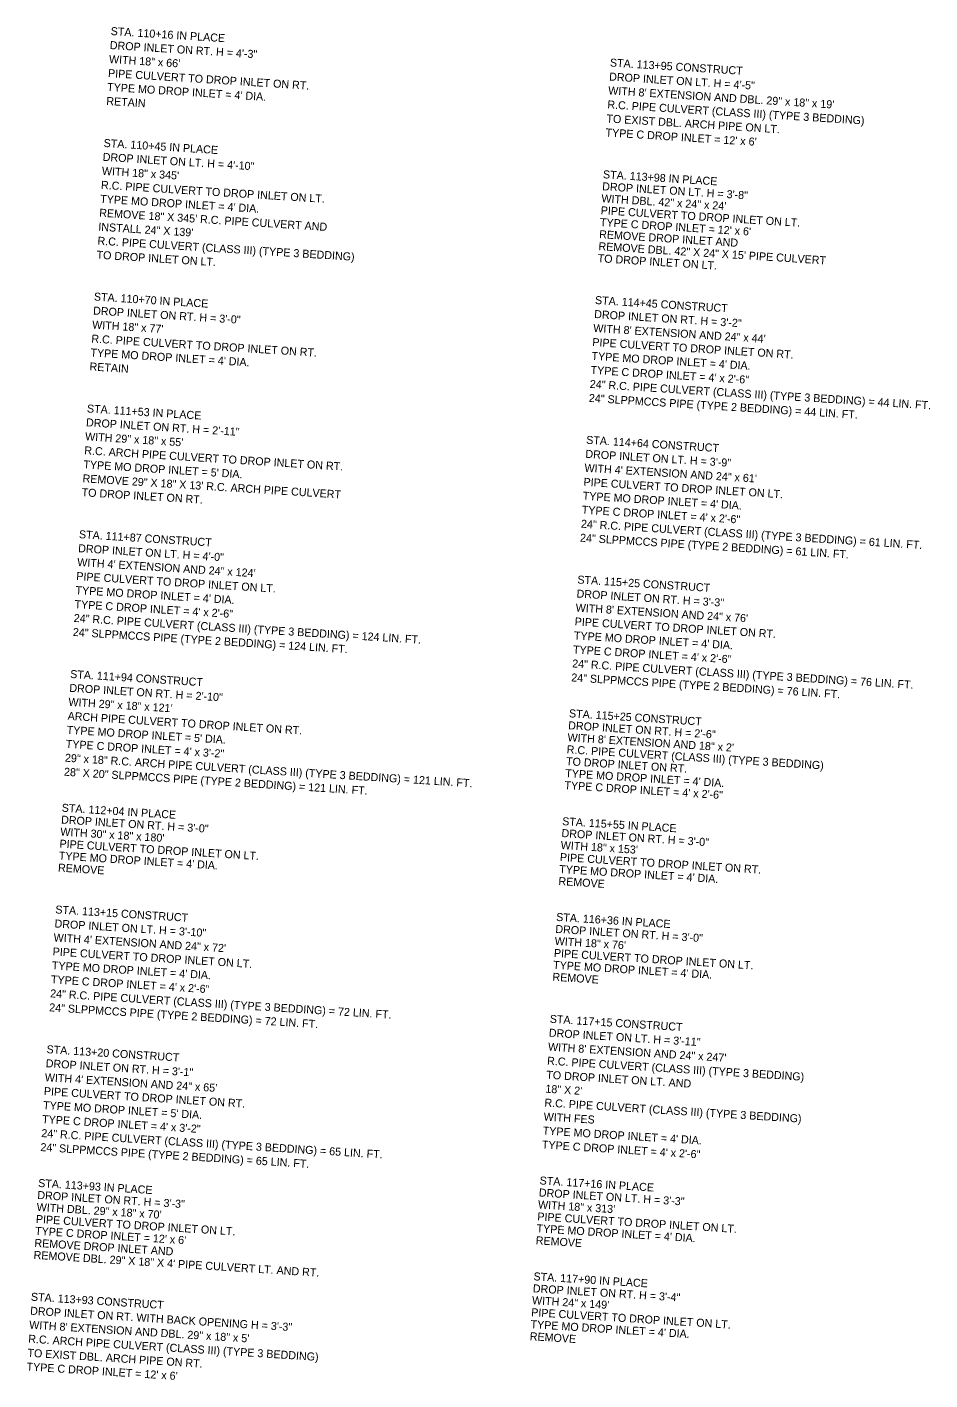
# Model space of a CAD drawing. Extents: x 660729 to 669183, y 641696 to 736523.
# Drawn here: x 660729 to 661406, y 641803 to 642818 of the extents above; entities that cross this region are included whole.
import ezdxf

# ---------------------------------------------------------------- set-up
doc = ezdxf.new("R2010")
doc.units = 0
doc.layers.add('T_Indications', color=7, linetype='Continuous')

msp = doc.modelspace()

# ---------------------------------------------------------------- texts
at = {"layer": 'T_Indications'}
for s, p in [('STA. 110+16 IN PLACE', (660791.3, 642812)), ('DROP INLET ON RT. H = 4\'-3"', (660790.6, 642801.5)), ('WITH 18" x 66\'', (660790, 642791)), ('STA. 113+95 CONSTRUCT', (661165.5, 642788.4)), ('PIPE CULVERT TO DROP INLET ON RT.', (660789.3, 642780.5)), ('DROP INLET ON LT. H = 4\'-5"', (661164.9, 642777.9)), ("TYPE MO DROP INLET = 4' DIA.", (660788.6, 642770.1)), ('WITH 8\' EXTENSION AND DBL. 29" x 18" x 19\'', (661164.2, 642767.5)), ('RETAIN', (660788, 642759.6)), ('R.C. PIPE CULVERT (CLASS III) (TYPE 3 BEDDING)', (661163.6, 642757)), ('TO EXIST DBL. ARCH PIPE ON LT.', (661162.9, 642746.5)), ("TYPE C DROP INLET = 12' x 6'", (661162.2, 642736)), ('STA. 110+45 IN PLACE', (660786, 642728.1)), ('DROP INLET ON LT. H = 4\'-10"', (660785.3, 642717.7)), ('WITH 18" x 345\'', (660784.7, 642707.2)), ('STA. 113+98 IN PLACE', (661160.3, 642704.6)), ('R.C. PIPE CULVERT TO DROP INLET ON LT.', (660784, 642696.7)), ('DROP INLET ON LT. H = 3\'-8"', (661159.7, 642695.6)), ("TYPE MO DROP INLET = 4' DIA.", (660783.4, 642686.2)), ('WITH DBL. 42" x 24" x 24\'', (661159.1, 642686.6)), ('REMOVE 18" X 345\' R.C. PIPE CULVERT AND', (660782.7, 642675.8)), ('PIPE CULVERT TO DROP INLET ON LT.', (661158.6, 642677.6)), ('INSTALL 24" X 139\'', (660782, 642665.3)), ("TYPE C DROP INLET = 12' x 6'", (661158, 642668.7)), ('R.C. PIPE CULVERT (CLASS III) (TYPE 3 BEDDING)', (660781.4, 642654.8)), ('REMOVE DROP INLET AND', (661157.4, 642659.7)), ('TO DROP INLET ON LT.', (660780.7, 642644.3)), ('REMOVE DBL. 42" X 24" X 15\' PIPE CULVERT', (661156.9, 642650.7)), ('TO DROP INLET ON LT.', (661156.3, 642641.7)), ('STA. 110+70 IN PLACE', (660778.7, 642612.9)), ('DROP INLET ON RT. H = 3\'-0"', (660778.1, 642602.4)), ('STA. 114+45 CONSTRUCT', (661154.3, 642610.3)), ('WITH 18" x 77\'', (660777.4, 642591.9)), ('DROP INLET ON RT. H = 3\'-2"', (661153.7, 642599.8)), ('R.C. PIPE CULVERT TO DROP INLET ON RT.', (660776.8, 642581.4)), ('WITH 8\' EXTENSION AND 24" x 44\'', (661153, 642589.3)), ('PIPE CULVERT TO DROP INLET ON RT.', (661152.3, 642578.8)), ("TYPE MO DROP INLET = 4' DIA.", (660776.1, 642571)), ("TYPE MO DROP INLET = 4' DIA.", (661151.7, 642568.4)), ('RETAIN', (660775.4, 642560.5)), ('TYPE C DROP INLET = 4\' x 2\'-6"', (661151, 642557.9)), ('24" R.C. PIPE CULVERT (CLASS III) (TYPE 3 BEDDING) = 44 LIN. FT.', (661150.4, 642547.4)), ('24" SLPPMCCS PIPE (TYPE 2 BEDDING) = 44 LIN. FT.', (661149.7, 642536.9)), ('STA. 111+53 IN PLACE', (660773.5, 642529)), ('DROP INLET ON RT. H = 2\'-11"', (660772.8, 642518.6)), ('WITH 29" x 18" x 55\'', (660772.1, 642508.1)), ('STA. 114+64 CONSTRUCT', (661147.7, 642505.5)), ('R.C. ARCH PIPE CULVERT TO DROP INLET ON RT.', (660771.5, 642497.6)), ('DROP INLET ON LT. H = 3\'-9"', (661147.1, 642495)), ("TYPE MO DROP INLET = 5' DIA.", (660770.8, 642487.1)), ('WITH 4\' EXTENSION AND 24" x 61\'', (661146.4, 642484.5)), ('REMOVE 29" X 18" X 13\' R.C. ARCH PIPE CULVERT', (660770.2, 642476.6)), ('PIPE CULVERT TO DROP INLET ON LT.', (661145.7, 642474)), ('TO DROP INLET ON RT.', (660769.5, 642466.2)), ("TYPE MO DROP INLET = 4' DIA.", (661145.1, 642463.6)), ('TYPE C DROP INLET = 4\' x 2\'-6"', (661144.4, 642453.1)), ('24" R.C. PIPE CULVERT (CLASS III) (TYPE 3 BEDDING) = 61 LIN. FT.', (661143.8, 642442.6)), ('STA. 111+87 CONSTRUCT', (660767.5, 642434.7)), ('24" SLPPMCCS PIPE (TYPE 2 BEDDING) = 61 LIN. FT.', (661143.1, 642432.1)), ('DROP INLET ON LT. H = 4\'-0"', (660766.9, 642424.2)), ('WITH 4\' EXTENSION AND 24" x 124\'', (660766.2, 642413.8)), ('PIPE CULVERT TO DROP INLET ON LT.', (660765.5, 642403.3)), ('STA. 115+25 CONSTRUCT', (661141.1, 642400.7)), ("TYPE MO DROP INLET = 4' DIA.", (660764.9, 642392.8)), ('DROP INLET ON RT. H = 3\'-3"', (661140.5, 642390.2)), ('TYPE C DROP INLET = 4\' x 2\'-6"', (660764.2, 642382.3)), ('WITH 8\' EXTENSION AND 24" x 76\'', (661139.8, 642379.7)), ('24" R.C. PIPE CULVERT (CLASS III) (TYPE 3 BEDDING) = 124 LIN. FT.', (660763.6, 642371.9)), ('PIPE CULVERT TO DROP INLET ON RT.', (661139.1, 642369.3)), ('24" SLPPMCCS PIPE (TYPE 2 BEDDING) = 124 LIN. FT.', (660762.9, 642361.4)), ("TYPE MO DROP INLET = 4' DIA.", (661138.5, 642358.8)), ('TYPE C DROP INLET = 4\' x 2\'-6"', (661137.8, 642348.3)), ('24" R.C. PIPE CULVERT (CLASS III) (TYPE 3 BEDDING) = 76 LIN. FT.', (661137.2, 642337.8)), ('STA. 111+94 CONSTRUCT', (660760.9, 642329.9)), ('DROP INLET ON RT. H = 2\'-10"', (660760.3, 642319.5)), ('24" SLPPMCCS PIPE (TYPE 2 BEDDING) = 76 LIN. FT.', (661136.5, 642327.3)), ('WITH 29" x 18" x 121\'', (660759.6, 642309)), ('ARCH PIPE CULVERT TO DROP INLET ON RT.', (660759, 642298.5)), ('STA. 115+25 CONSTRUCT', (661134.8, 642300.4)), ("TYPE MO DROP INLET = 5' DIA.", (660758.3, 642288)), ('DROP INLET ON RT. H = 2\'-6"', (661134.2, 642291.4)), ('TYPE C DROP INLET = 4\' x 3\'-2"', (660757.6, 642277.5)), ('WITH 8\' EXTENSION AND 18" x 2\'', (661133.7, 642282.4)), ('29" x 18" R.C. ARCH PIPE CULVERT (CLASS III) (TYPE 3 BEDDING) = 121 LIN. FT.', (660757, 642267.1)), ('R.C. PIPE CULVERT (CLASS III) (TYPE 3 BEDDING)', (661133.1, 642273.4)), ('28" X 20" SLPPMCCS PIPE (TYPE 2 BEDDING) = 121 LIN. FT.', (660756.3, 642256.6)), ('TO DROP INLET ON RT.', (661132.6, 642264.5)), ('TYPE C DROP INLET = 4\' x 2\'-6"', (661131.4, 642246.5)), ("TYPE MO DROP INLET = 4' DIA.", (661132, 642255.5)), ('STA. 112+04 IN PLACE', (660754.6, 642229.6)), ('DROP INLET ON RT. H = 3\'-0"', (660754.1, 642220.7)), ('STA. 115+55 IN PLACE', (661129.7, 642219.5)), ('WITH 30" x 18" x 180\'', (660753.5, 642211.7)), ('DROP INLET ON RT. H = 3\'-0"', (661129.2, 642210.6)), ('PIPE CULVERT TO DROP INLET ON LT.', (660752.9, 642202.7)), ('WITH 18" x 153\'', (661128.6, 642201.6)), ("TYPE MO DROP INLET = 4' DIA.", (660752.4, 642193.7)), ('PIPE CULVERT TO DROP INLET ON RT.', (661128, 642192.6)), ('REMOVE', (660751.8, 642184.7)), ("TYPE MO DROP INLET = 4' DIA.", (661127.5, 642183.6)), ('REMOVE', (661126.9, 642174.6)), ('STA. 113+15 CONSTRUCT', (660749.8, 642153.3)), ('STA. 116+36 IN PLACE', (661125.2, 642147.7)), ('DROP INLET ON LT. H = 3\'-10"', (660749.2, 642142.8)), ('DROP INLET ON RT. H = 3\'-0"', (661124.6, 642138.7)), ('WITH 4\' EXTENSION AND 24" x 72\'', (660748.5, 642132.3)), ('WITH 18" x 76\'', (661124.1, 642129.7)), ('PIPE CULVERT TO DROP INLET ON LT.', (660747.8, 642121.8)), ('PIPE CULVERT TO DROP INLET ON LT.', (661123.5, 642120.7)), ("TYPE MO DROP INLET = 4' DIA.", (660747.2, 642111.4)), ("TYPE MO DROP INLET = 4' DIA.", (661122.9, 642111.8)), ('TYPE C DROP INLET = 4\' x 2\'-6"', (660746.5, 642100.9)), ('REMOVE', (661122.4, 642102.8)), ('24" R.C. PIPE CULVERT (CLASS III) (TYPE 3 BEDDING) = 72 LIN. FT.', (660745.9, 642090.4)), ('24" SLPPMCCS PIPE (TYPE 2 BEDDING) = 72 LIN. FT.', (660745.2, 642079.9)), ('STA. 117+15 CONSTRUCT', (661120.4, 642071.3)), ('DROP INLET ON LT. H = 3\'-11"', (661119.7, 642060.9)), ('STA. 113+20 CONSTRUCT', (660743.2, 642048.5)), ('WITH 8\' EXTENSION AND 24" x 247\'', (661119.1, 642050.4)), ('DROP INLET ON RT. H = 3\'-1"', (660742.6, 642038)), ('R.C. PIPE CULVERT (CLASS III) (TYPE 3 BEDDING)', (661118.4, 642039.9)), ('WITH 4\' EXTENSION AND 24" x 65\'', (660741.9, 642027.5)), ('TO DROP INLET ON LT. AND', (661117.8, 642029.4)), ('PIPE CULVERT TO DROP INLET ON RT.', (660741.2, 642017.1)), ('18" X 2\'', (661117.1, 642018.9)), ("TYPE MO DROP INLET = 5' DIA.", (660740.6, 642006.6)), ('R.C. PIPE CULVERT (CLASS III) (TYPE 3 BEDDING)', (661116.4, 642008.5)), ('TYPE C DROP INLET = 4\' x 3\'-2"', (660739.9, 641996.1)), ('WITH FES', (661115.8, 641998)), ('24" R.C. PIPE CULVERT (CLASS III) (TYPE 3 BEDDING) = 65 LIN. FT.', (660739.3, 641985.6)), ("TYPE MO DROP INLET = 4' DIA.", (661115.1, 641987.5)), ('24" SLPPMCCS PIPE (TYPE 2 BEDDING) = 65 LIN. FT.', (660738.6, 641975.1)), ('TYPE C DROP INLET = 4\' x 2\'-6"', (661114.5, 641977)), ('STA. 113+93 IN PLACE', (660736.9, 641948.2)), ('STA. 117+16 IN PLACE', (661112.8, 641950.1)), ('DROP INLET ON RT. H = 3\'-3"', (660736.3, 641939.2)), ('WITH 18" x 313\'', (661111.6, 641932.1)), ('DROP INLET ON LT. H = 3\'-3"', (661112.2, 641941.1)), ('WITH DBL. 29" x 18" x 70\'', (660735.8, 641930.2)), ('PIPE CULVERT TO DROP INLET ON LT.', (661111.1, 641923.1)), ("TYPE C DROP INLET = 12' x 6'", (660734.6, 641912.3)), ('PIPE CULVERT TO DROP INLET ON LT.', (660735.2, 641921.2)), ("TYPE MO DROP INLET = 4' DIA.", (661110.5, 641914.2)), ('REMOVE DROP INLET AND ', (660734.1, 641903.3)), ('REMOVE', (661109.9, 641905.2)), ('REMOVE DBL. 29" X 18" X 4\' PIPE CULVERT LT. AND RT. ', (660733.5, 641894.3)), ('STA. 117+90 IN PLACE', (661108.2, 641878.2)), ('STA. 113+93 CONSTRUCT', (660731.5, 641862.9)), ('DROP INLET ON RT. H = 3\'-4"', (661107.7, 641869.2)), ('DROP INLET ON RT. WITH BACK OPENING H = 3\'-3"', (660730.9, 641852.4)), ('PIPE CULVERT TO DROP INLET ON LT.', (661106.5, 641851.3)), ('WITH 24" x 149\'', (661107.1, 641860.3)), ('WITH 8\' EXTENSION AND DBL. 29" x 18" x 5\'', (660730.2, 641841.9)), ("TYPE MO DROP INLET = 4' DIA.", (661106, 641842.3)), ('R.C. ARCH PIPE CULVERT (CLASS III) (TYPE 3 BEDDING)', (660729.5, 641831.4)), ('REMOVE', (661105.4, 641833.3)), ('TO EXIST DBL. ARCH PIPE ON RT.', (660728.9, 641820.9)), ("TYPE C DROP INLET = 12' x 6'", (660728.2, 641810.5))]:
    msp.add_text(s, height=6, rotation=356.3979, dxfattribs=at).set_placement(p)

doc.saveas('drawing.dxf')
